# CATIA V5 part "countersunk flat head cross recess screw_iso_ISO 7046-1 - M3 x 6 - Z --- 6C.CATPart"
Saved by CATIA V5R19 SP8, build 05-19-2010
Part number: countersunk flat head cross recess screw_iso_ISO 7046-1 - M3 x 6 - Z --- 6C
Revision: ANY
Definition: UNKNOWN
Nomenclature: countersunk flat head cross recess screw_iso_ISO 7046-1 - M3 x 6 - Z --- 6C
Source: Unknown
Bounding box of the stored display mesh (mm): x 0 to 6, y -2.741 to 2.741, z -2.75 to 2.75
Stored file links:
  D:\Documents\1_Travail\1 - ac-limoges.fr\ac-limoges.fr\Emmanuel Maynard - STI2D_Turgot\2 -2I2D\2_SEQUENCE_Serrure_Biométrique\5-Spé_ITEC\Serrure_Bio_Eleve\countersunk flat head cross recess screw_iso_ISO 7046-1 - M3 x 6 - Z --- 6C.CATPart
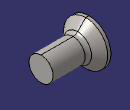
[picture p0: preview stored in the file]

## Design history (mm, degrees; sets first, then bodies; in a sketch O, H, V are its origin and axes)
Body1 "RecessCore" (main body)
  Solid1: solid without history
